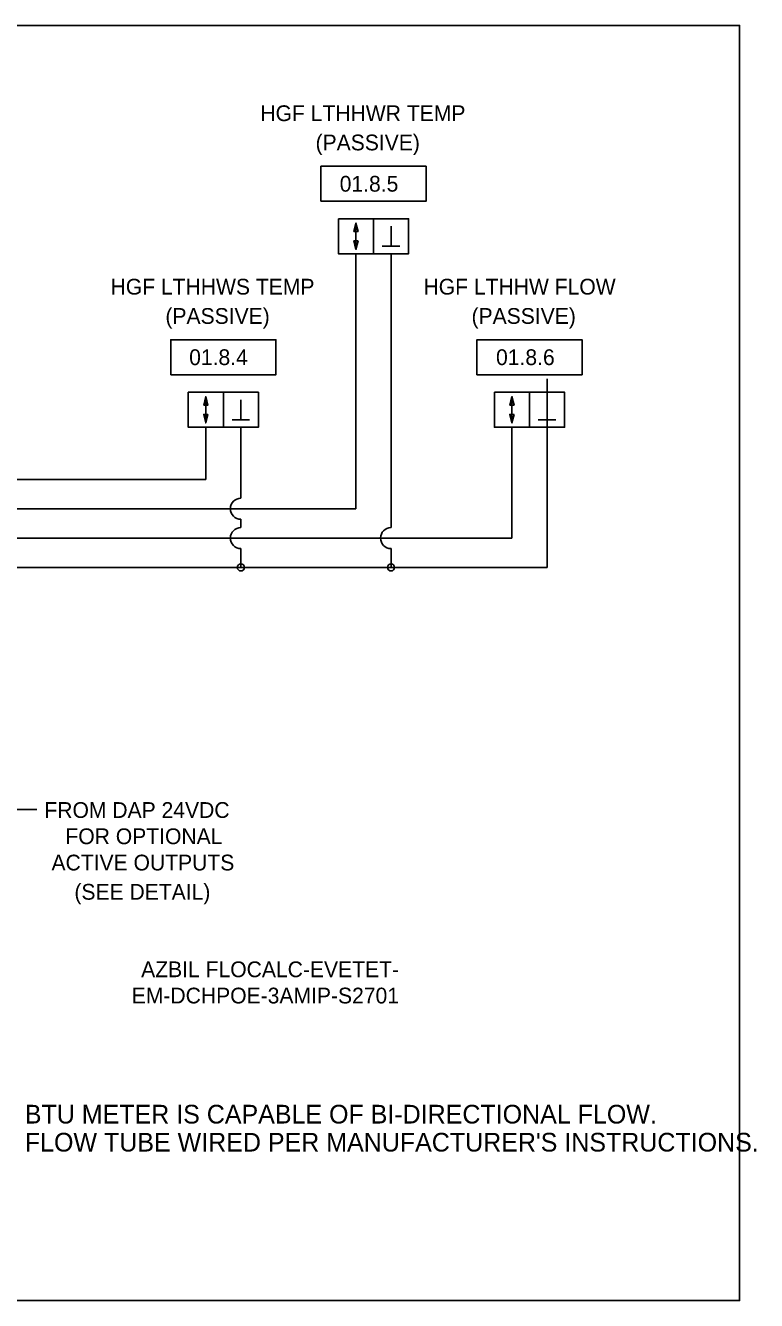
# Model space of a CAD drawing. Extents: x 10010.3 to 10109.1, y 10088 to 10139.5.
# Drawn here: x 10083.08 to 10109.15, y 10093.97 to 10139.47 of the extents above; entities that cross this region are included whole.
import ezdxf

# ---------------------------------------------------------------- set-up
doc = ezdxf.new("R2010")
doc.units = 0
for name, color, linetype in [('Default', 7, 'Continuous'), ('G-DETL-GRID', 7, 'Continuous'), ('G-DETL-LINE', 7, 'Continuous')]:
    doc.layers.add(name, color=color, linetype=linetype)

# ---------------------------------------------------------------- blocks, each defined once
blk = doc.blocks.new('TERARR1')
for p, q in [((-0.67, 0.17), (-0.67, -0.17)), ((0, 0), (-0.67, 0.17)), ((-0.67, -0.17), (0, 0))]:
    blk.add_line(p, q)
blk.add_lwpolyline([(-0.67, 0.17), (0, 0), (-0.67, -0.17), (-0.67, 0.17)])

msp = doc.modelspace()

# ---------------------------------------------------------------- linework, layer by layer
msp.add_line((10082.496, 10111.49), (10083.487, 10111.49))
at = {"layer": 'G-DETL-GRID'}
msp.add_lwpolyline([(10059.407, 10139.467), (10108.549, 10139.467), (10108.549, 10093.967), (10059.407, 10093.967)], close=True, dxfattribs=at)
at = {"layer": 'G-DETL-LINE'}
for p, q in [((10094.867, 10132.413), (10094.867, 10131.476)), ((10096.117, 10131.588), (10096.117, 10132.301)), ((10095.804, 10131.588), (10096.429, 10131.588)), ((10094.867, 10131.319), (10094.867, 10122.222)), ((10096.117, 10131.319), (10096.117, 10121.549)), ((10101.679, 10125.129), (10101.679, 10126.855)), ((10101.679, 10126.855), (10101.679, 10120.126)), ((10089.512, 10126.223), (10089.512, 10125.285)), ((10090.762, 10125.398), (10090.762, 10126.11)), ((10100.429, 10126.223), (10100.429, 10125.285)), ((10101.679, 10125.398), (10101.679, 10126.11)), ((10089.512, 10125.129), (10089.512, 10123.27)), ((10090.45, 10125.398), (10091.075, 10125.398)), ((10090.762, 10125.129), (10090.762, 10122.597)), ((10100.429, 10125.129), (10100.429, 10121.174)), ((10101.367, 10125.398), (10101.992, 10125.398)), ((10062.054, 10123.27), (10089.512, 10123.27)), ((10065.179, 10122.222), (10094.867, 10122.222)), ((10090.762, 10121.847), (10090.762, 10121.549)), ((10068.304, 10121.174), (10100.429, 10121.174)), ((10090.762, 10120.799), (10090.762, 10120.126)), ((10096.117, 10120.799), (10096.117, 10120.126)), ((10071.429, 10120.126), (10101.679, 10120.126))]:
    msp.add_line(p, q, dxfattribs=at)
for points in [[(10093.617, 10133.194), (10097.367, 10133.194), (10097.367, 10134.444), (10093.617, 10134.444), (10093.617, 10133.194)], [(10094.242, 10132.569), (10095.492, 10132.569), (10095.492, 10131.319), (10094.242, 10131.319), (10094.242, 10132.569)], [(10095.492, 10132.569), (10096.742, 10132.569), (10096.742, 10131.319), (10095.492, 10131.319), (10095.492, 10132.569)], [(10088.262, 10127.004), (10092.012, 10127.004), (10092.012, 10128.254), (10088.262, 10128.254), (10088.262, 10127.004)], [(10099.179, 10127.004), (10102.929, 10127.004), (10102.929, 10128.254), (10099.179, 10128.254), (10099.179, 10127.004)], [(10088.887, 10126.379), (10090.137, 10126.379), (10090.137, 10125.129), (10088.887, 10125.129), (10088.887, 10126.379)], [(10090.137, 10126.379), (10091.387, 10126.379), (10091.387, 10125.129), (10090.137, 10125.129), (10090.137, 10126.379)], [(10099.804, 10126.379), (10101.054, 10126.379), (10101.054, 10125.129), (10099.804, 10125.129), (10099.804, 10126.379)], [(10101.054, 10126.379), (10102.304, 10126.379), (10102.304, 10125.129), (10101.054, 10125.129), (10101.054, 10126.379)]]:
    msp.add_lwpolyline(points, dxfattribs=at)
for centre, radius, start, end in [((10090.762, 10122.222), 0.375, 90, 270), ((10090.762, 10121.174), 0.375, 90, 270), ((10096.117, 10121.174), 0.375, 90, 270), ((10090.762, 10120.126), 0.125, 0, 180), ((10090.762, 10120.126), 0.125, 180, 0), ((10096.117, 10120.126), 0.125, 0, 180), ((10096.117, 10120.126), 0.125, 180, 0)]:
    msp.add_arc(centre, radius, start, end, dxfattribs=at)

# ---------------------------------------------------------------- block references
at = {"layer": 'G-DETL-LINE', "xscale": 0.45, "yscale": 0.45}
for p, rotation in [((10094.867, 10132.413), 90), ((10094.867, 10131.476), -90.00000000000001), ((10089.512, 10126.223), 90), ((10100.429, 10126.223), 90), ((10089.512, 10125.285), -90.00000000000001), ((10100.429, 10125.285), -90.00000000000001)]:
    msp.add_blockref('TERARR1', p, dxfattribs=dict(at, rotation=rotation))

# ---------------------------------------------------------------- texts
at = {"layer": 'Default'}
for s, p in [('HGF LTHHWR TEMP', (10091.457, 10136.055)), ('(PASSIVE)', (10093.426, 10135.011)), ('HGF LTHHWS TEMP', (10086.115, 10129.865)), ('HGF LTHHW FLOW', (10097.274, 10129.865)), ('(PASSIVE)', (10088.071, 10128.82)), ('(PASSIVE)', (10098.988, 10128.82)), ('FROM DAP 24VDC ', (10083.755, 10111.189)), ('FOR OPTIONAL ', (10084.505, 10110.252)), ('ACTIVE OUTPUTS ', (10084.009, 10109.314)), ('(SEE DETAIL)', (10084.826, 10108.27)), ('AZBIL FLOCALC-EVETET-', (10087.206, 10105.505)), ('EM-DCHPOE-3AMIP-S2701', (10086.871, 10104.568))]:
    msp.add_text(s, height=0.5625, dxfattribs=at).set_placement(p)
at = {"layer": 'G-DETL-LINE'}
for s, height, p in [('01.8.5', 0.5625, (10094.287, 10133.538)), ('01.8.4', 0.5625, (10088.918, 10127.348)), ('01.8.6', 0.5625, (10099.862, 10127.348)), ('BTU METER IS CAPABLE OF BI-DIRECTIONAL FLOW.', 0.66667, (10083.058, 10100.283)), ("FLOW TUBE WIRED PER MANUFACTURER'S INSTRUCTIONS.", 0.66667, (10083.058, 10099.283))]:
    msp.add_text(s, height=height, dxfattribs=at).set_placement(p)

doc.saveas('drawing.dxf')
